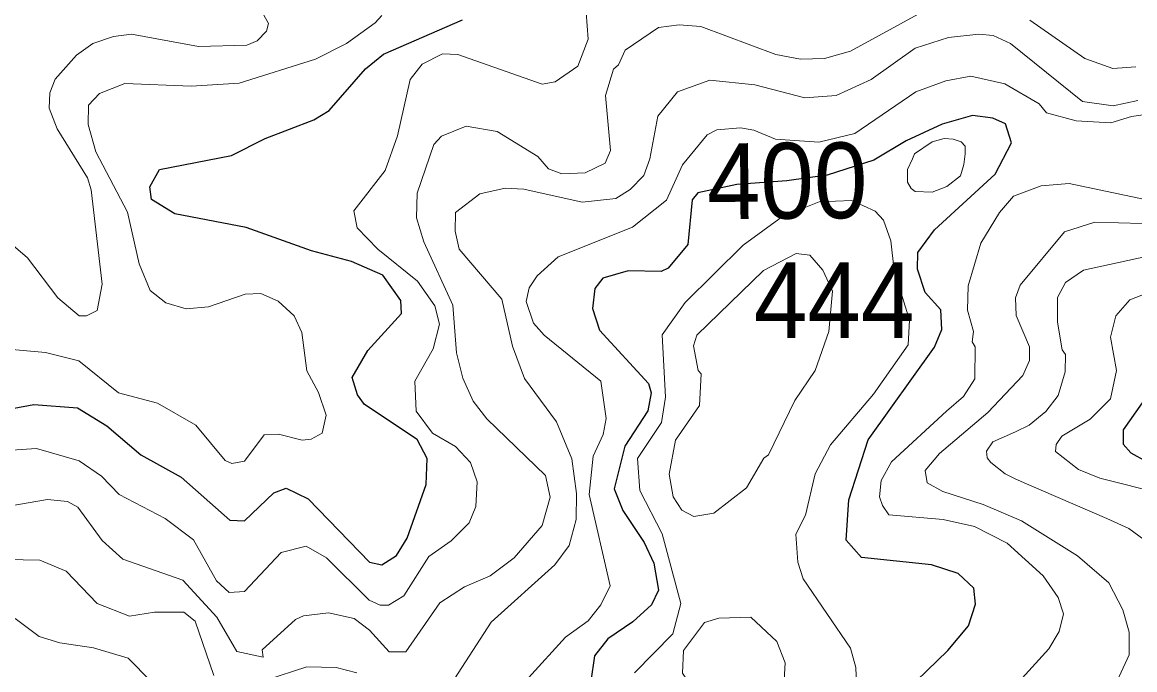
# Model space of a CAD drawing. Extents: x 673.6 to 698.9, y 7012 to 7040.1.
# Drawn here: x 685.993 to 687.168, y 7014.316 to 7015.001 of the extents above; entities that cross this region are included whole.
import ezdxf
from ezdxf.enums import TextEntityAlignment as Align

# ---------------------------------------------------------------- set-up
doc = ezdxf.new("R2010")
doc.units = 0
doc.header["$LTSCALE"] = 0.032
doc.layers.add('1', color=7, linetype='Continuous', lineweight=25)
doc.layers.add('2', color=7, linetype='Continuous', lineweight=13)
doc.layers.add('21', color=7, linetype='Continuous')
doc.layers.add('61', color=7, linetype='Continuous')

msp = doc.modelspace()

# ---------------------------------------------------------------- linework, layer by layer
at = {"layer": '1'}
for points in [[(685.9233, 7014.5815), (686.0049, 7014.5967), (686.0511, 7014.5932), (686.0823, 7014.5743), (686.1179, 7014.5436), (686.1606, 7014.5201), (686.2119, 7014.4745), (686.2274, 7014.474), (686.2584, 7014.5035), (686.2716, 7014.5085), (686.2948, 7014.4972), (686.3595, 7014.43), (686.3726, 7014.4275), (686.3882, 7014.4372), (686.3992, 7014.4555), (686.4194, 7014.5121), (686.4205, 7014.5397), (686.4098, 7014.5597), (686.3541, 7014.5968), (686.3469, 7014.6071), (686.3411, 7014.6251), (686.3577, 7014.6536), (686.3933, 7014.6929), (686.3927, 7014.7067), (686.3738, 7014.7335), (686.3404, 7014.7478), (686.2983, 7014.7589), (686.2292, 7014.7838), (686.154, 7014.7982), (686.1294, 7014.8132), (686.1274, 7014.8268), (686.1379, 7014.8451), (686.2139, 7014.8598), (686.2492, 7014.8779), (686.3009, 7014.8976), (686.317, 7014.9074), (686.3552, 7014.9512), (686.3742, 7014.967), (686.4576, 7015.0031)], [(686.9151, 7014.2833), (686.9702, 7014.3369), (686.9923, 7014.363), (686.9995, 7014.3858), (686.9979, 7014.4028), (686.9813, 7014.4182), (686.9531, 7014.4274), (686.8793, 7014.4351), (686.8629, 7014.4535), (686.8658, 7014.496), (686.8863, 7014.5595), (686.9563, 7014.6574), (686.964, 7014.6759), (686.9628, 7014.6968), (686.9463, 7014.7151), (686.9383, 7014.7397), (686.9386, 7014.7574), (686.9561, 7014.7813), (687.0204, 7014.84), (687.0375, 7014.873), (687.0314, 7014.8931), (687.018, 7014.8991), (686.9964, 7014.9021), (686.9643, 7014.8928), (686.9264, 7014.8751), (686.8921, 7014.8547), (686.8428, 7014.839), (686.8004, 7014.833), (686.7475, 7014.829), (686.7062, 7014.8205), (686.7002, 7014.813), (686.6956, 7014.7657), (686.6748, 7014.7408), (686.6675, 7014.7373), (686.6326, 7014.738), (686.606, 7014.7303), (686.5975, 7014.7194), (686.5949, 7014.6983), (686.6024, 7014.6751), (686.6541, 7014.6188), (686.6569, 7014.6092), (686.6535, 7014.5902), (686.6292, 7014.5528), (686.618, 7014.5076), (686.6272, 7014.4848), (686.6496, 7014.4508), (686.6597, 7014.4291), (686.6647, 7014.4007), (686.6574, 7014.385), (686.6377, 7014.367), (686.6113, 7014.3493), (686.597, 7014.3312), (686.5932, 7014.3046)], [(687.1757, 7014.5984), (687.1555, 7014.5698), (687.1554, 7014.5548), (687.1637, 7014.5456), (687.1802, 7014.5365)]]:
    msp.add_lwpolyline(points, dxfattribs=at)
at = {"layer": '2'}
for points in [[(685.9029, 7014.6617), (686.0172, 7014.6518), (686.0525, 7014.643), (686.0943, 7014.6091), (686.1358, 7014.5982), (686.1761, 7014.5749), (686.2071, 7014.5377), (686.214, 7014.5343), (686.2276, 7014.5369), (686.2484, 7014.5646), (686.2633, 7014.5655), (686.2886, 7014.559), (686.2981, 7014.56), (686.3097, 7014.5665), (686.3137, 7014.5853), (686.3056, 7014.6095), (686.2933, 7014.6324), (686.288, 7014.6728), (686.28, 7014.6903), (686.263, 7014.7058), (686.2447, 7014.7141), (686.2284, 7014.7134), (686.1895, 7014.7), (686.1659, 7014.6979), (686.1445, 7014.7043), (686.1278, 7014.7171), (686.1164, 7014.7453), (686.1038, 7014.8), (686.0704, 7014.8636), (686.0624, 7014.8926), (686.0628, 7014.913), (686.0743, 7014.9254), (686.101, 7014.9359), (686.1713, 7014.9329), (686.222, 7014.9362), (686.3025, 7014.9617), (686.3354, 7014.9782), (686.3657, 7014.9998), (686.3724, 7015.0078)], [(685.9656, 7014.5475), (686.008, 7014.5501), (686.053, 7014.5372), (686.0765, 7014.5209), (686.0953, 7014.5015), (686.1439, 7014.4763), (686.1738, 7014.4539), (686.198, 7014.4103), (686.2115, 7014.3981), (686.2277, 7014.399), (686.2661, 7014.4404), (686.2926, 7014.4472), (686.3143, 7014.4349), (686.3591, 7014.3901), (686.3708, 7014.3848), (686.3796, 7014.3848), (686.3959, 7014.3946), (686.4223, 7014.4363), (686.4457, 7014.4526), (686.4648, 7014.4718), (686.4717, 7014.4889), (686.4731, 7014.5149), (686.4661, 7014.5355), (686.4503, 7014.5522), (686.426, 7014.5666), (686.4088, 7014.5896), (686.4075, 7014.6213), (686.4269, 7014.6555), (686.4336, 7014.6816), (686.4285, 7014.7008), (686.4102, 7014.727), (686.3682, 7014.7608), (686.3464, 7014.7833), (686.343, 7014.8014), (686.3762, 7014.8441), (686.3892, 7014.8807), (686.4025, 7014.9399), (686.4152, 7014.9561), (686.4367, 7014.9671), (686.4527, 7014.9665), (686.5419, 7014.9353), (686.5558, 7014.9377), (686.5795, 7014.954), (686.5906, 7014.9826), (686.5883, 7015.0109)], [(686.2481, 7015.008), (686.2529, 7014.9992), (686.2507, 7014.991), (686.2408, 7014.9808), (686.2299, 7014.9764), (686.1791, 7014.9748), (686.1083, 7014.9878), (686.089, 7014.9855), (686.0673, 7014.978), (686.0501, 7014.9656), (686.0277, 7014.9405), (686.0221, 7014.9261), (686.0214, 7014.9098), (686.0297, 7014.8879), (686.0617, 7014.8361), (686.0656, 7014.8235), (686.0771, 7014.7239), (686.0719, 7014.696), (686.0606, 7014.6905), (686.0528, 7014.6905), (686.0304, 7014.7094), (685.9985, 7014.7518), (685.9679, 7014.7775)], [(686.9466, 7015.0133), (686.8676, 7014.9699), (686.84, 7014.9622), (686.8147, 7014.9616), (686.7887, 7014.9666), (686.7095, 7014.9962), (686.6866, 7014.9978), (686.6646, 7014.9951), (686.6297, 7014.9709), (686.6224, 7014.9557), (686.6171, 7014.9511), (686.6088, 7014.9233), (686.6142, 7014.8651), (686.6083, 7014.8517), (686.5874, 7014.8413), (686.5626, 7014.8404), (686.5487, 7014.8458), (686.5372, 7014.8586), (686.4943, 7014.8851), (686.4616, 7014.8909), (686.4356, 7014.8801), (686.4274, 7014.8713), (686.4098, 7014.8199), (686.4091, 7014.794), (686.417, 7014.7684), (686.4476, 7014.7017), (686.4515, 7014.6514), (686.4582, 7014.6244), (686.4692, 7014.6001), (686.4833, 7014.5816), (686.5453, 7014.5218), (686.5503, 7014.4988), (686.542, 7014.469), (686.5124, 7014.4347), (686.487, 7014.4156), (686.4597, 7014.4042), (686.4338, 7014.3871), (686.3979, 7014.3355), (686.3804, 7014.3355), (686.3597, 7014.3584), (686.3432, 7014.3707), (686.3162, 7014.3765)], [(687.1688, 7014.9534), (687.1447, 7014.9518), (687.1152, 7014.9623), (687.0571, 7015.0028)], [(687.1709, 7014.9178), (687.1448, 7014.9123), (687.1126, 7014.9169), (687.0365, 7014.9782), (687.0182, 7014.9864), (687.0032, 7014.9879), (686.9712, 7014.9846), (686.936, 7014.973), (686.8895, 7014.9401), (686.8525, 7014.923), (686.8192, 7014.9206), (686.7664, 7014.9343), (686.7191, 7014.9392), (686.6847, 7014.9272), (686.6639, 7014.9014), (686.6555, 7014.8561), (686.6492, 7014.8387), (686.6348, 7014.824), (686.6197, 7014.8142), (686.5842, 7014.8104), (686.5225, 7014.8243), (686.5027, 7014.8251), (686.4761, 7014.8193), (686.4502, 7014.7995), (686.4501, 7014.7797), (686.4544, 7014.7608), (686.4994, 7014.708), (686.5104, 7014.6582), (686.5234, 7014.6243), (686.5572, 7014.5783), (686.5733, 7014.5395), (686.5783, 7014.5027), (686.5777, 7014.4752), (686.5704, 7014.4478), (686.5553, 7014.4275), (686.4879, 7014.3666), (686.4416, 7014.2949)], [(687.1985, 7014.9058), (687.1643, 7014.9009), (687.1424, 7014.8943), (687.106, 7014.8963), (687.0747, 7014.905), (687.0668, 7014.9142), (687.0304, 7014.9355), (686.9947, 7014.9436), (686.9682, 7014.9385), (686.9367, 7014.927), (686.872, 7014.8829), (686.834, 7014.8738), (686.7885, 7014.877), (686.7656, 7014.8867), (686.7513, 7014.8891), (686.7264, 7014.8868), (686.7162, 7014.8816), (686.6901, 7014.85), (686.6733, 7014.8126), (686.6374, 7014.784), (686.5587, 7014.7528), (686.5367, 7014.7326), (686.5283, 7014.7199), (686.525, 7014.7056), (686.5329, 7014.6828), (686.5441, 7014.6699), (686.6037, 7014.6212), (686.6096, 7014.582), (686.6063, 7014.565), (686.5956, 7014.5422), (686.5916, 7014.5017), (686.6137, 7014.4051), (686.604, 7014.3851), (686.5904, 7014.3681), (686.5667, 7014.351), (686.5275, 7014.3079)], [(687.0487, 7014.3077), (687.0771, 7014.3385), (687.0878, 7014.3568), (687.0925, 7014.3756), (687.0867, 7014.3928), (687.071, 7014.4156), (687.033, 7014.4502), (686.9986, 7014.4677), (686.9655, 7014.4752), (686.9081, 7014.4801), (686.9012, 7014.49), (686.8982, 7014.4993), (686.9001, 7014.5165), (686.911, 7014.5363), (686.9691, 7014.5897), (686.9869, 7014.6052), (686.999, 7014.6237), (686.9991, 7014.6575), (686.9959, 7014.663), (686.9973, 7014.6739), (686.9912, 7014.6964), (686.9919, 7014.7221), (687.0053, 7014.767), (687.0248, 7014.7997), (687.0396, 7014.8169), (687.0688, 7014.8277), (687.0986, 7014.8301), (687.1771, 7014.8137)], [(686.8742, 7014.2923), (686.8733, 7014.3189), (686.8676, 7014.3392), (686.8176, 7014.4127), (686.8118, 7014.4301), (686.8099, 7014.4599), (686.8199, 7014.4797), (686.8302, 7014.5236), (686.8464, 7014.554), (686.8919, 7014.6078), (686.9286, 7014.6596), (686.93, 7014.6859), (686.9137, 7014.7384), (686.9102, 7014.7697), (686.9024, 7014.7916), (686.8935, 7014.8011), (686.8688, 7014.8121), (686.8346, 7014.8109), (686.7956, 7014.7954), (686.7541, 7014.765), (686.6928, 7014.7046), (686.6688, 7014.6703), (686.672, 7014.6046), (686.6681, 7014.5777), (686.6425, 7014.5396), (686.645, 7014.5057), (686.6687, 7014.46), (686.6885, 7014.3864), (686.6798, 7014.3545), (686.6394, 7014.3133)], [(687.0482, 7014.4739), (687.0077, 7014.4912), (686.9649, 7014.5048), (686.9486, 7014.5139), (686.9464, 7014.527), (686.9616, 7014.5448), (687.0126, 7014.5882), (687.0494, 7014.6274), (687.0566, 7014.6431), (687.0566, 7014.6577), (687.0426, 7014.6908), (687.0419, 7014.7094), (687.0467, 7014.7229), (687.0936, 7014.779), (687.1256, 7014.7892), (687.2007, 7014.7873)], [(687.1772, 7014.4541), (687.1615, 7014.4657), (687.1382, 7014.4763), (687.0511, 7014.5141), (687.0409, 7014.5184), (687.0308, 7014.5235), (687.0158, 7014.5356), (687.012, 7014.5405), (687.0111, 7014.5475), (687.0177, 7014.5574), (687.0418, 7014.568), (687.0564, 7014.575), (687.0738, 7014.5894), (687.087, 7014.6061), (687.0944, 7014.6313), (687.0945, 7014.6497), (687.0912, 7014.6545), (687.0863, 7014.6838), (687.0863, 7014.7097), (687.0945, 7014.7257), (687.1136, 7014.7385), (687.2186, 7014.7616)], [(687.1959, 7014.7203), (687.1624, 7014.7073), (687.1476, 7014.6904), (687.1423, 7014.6678), (687.1486, 7014.6326), (687.142, 7014.6028), (687.1208, 7014.5813), (687.0907, 7014.5632)], [(687.0907, 7014.5632), (687.0846, 7014.5545), (687.0841, 7014.5472), (687.1082, 7014.5279), (687.1307, 7014.5188), (687.1576, 7014.5122)], [(687.1576, 7014.5122), (687.1933, 7014.503)], [(686.2196, 7014.3358), (686.1982, 7014.3722), (686.1625, 7014.411), (686.0991, 7014.4334), (686.0773, 7014.4529), (686.0515, 7014.4882), (686.0407, 7014.4942), (686.0194, 7014.4965), (685.8966, 7014.4752)], [(687.1404, 7014.4085), (687.1073, 7014.4369), (687.0482, 7014.4739)], [(686.1952, 7014.3106), (686.1753, 7014.368), (686.1633, 7014.3772), (686.1323, 7014.3773), (686.1061, 7014.3732), (686.0719, 7014.3866), (686.0392, 7014.4208), (686.0113, 7014.4323), (685.9231, 7014.4341)], [(687.127, 7014.2818), (687.1472, 7014.3003), (687.1618, 7014.3322), (687.1618, 7014.3563), (687.1552, 7014.3798), (687.1404, 7014.4085)], [(686.1839, 7014.1906), (686.1665, 7014.2055), (686.1567, 7014.222), (686.1286, 7014.3045), (686.1046, 7014.3289), (686.0682, 7014.3397), (686.0324, 7014.3448), (686.0105, 7014.3515), (685.9852, 7014.3705)], [(686.3162, 7014.3765), (686.2899, 7014.3734), (686.2815, 7014.3697), (686.2461, 7014.3375), (686.2474, 7014.3299), (686.2196, 7014.3358)], [(686.346, 7014.3134), (686.3243, 7014.3189), (686.2932, 7014.3197), (686.2499, 7014.3055)]]:
    msp.add_lwpolyline(points, dxfattribs=at)
for points in [[(686.9329, 7014.8562), (686.9277, 7014.845), (686.9277, 7014.8316), (686.9315, 7014.8249), (686.9359, 7014.8219), (686.9538, 7014.8212), (686.9694, 7014.8272), (686.9836, 7014.8383), (686.9873, 7014.8502), (686.9888, 7014.8614), (686.9888, 7014.8696), (686.9843, 7014.8741), (686.9761, 7014.877), (686.9665, 7014.8778), (686.9538, 7014.8741), (686.9352, 7014.8614)], [(686.8448, 7014.6738), (686.8304, 7014.6328), (686.8088, 7014.6009), (686.7809, 7014.5437), (686.7759, 7014.5399), (686.7576, 7014.5086), (686.7233, 7014.4818), (686.702, 7014.4785), (686.6895, 7014.4851), (686.6803, 7014.4993), (686.6762, 7014.5232), (686.6828, 7014.5589), (686.7082, 7014.5955), (686.7098, 7014.6292), (686.7065, 7014.6327), (686.7016, 7014.6587), (686.7052, 7014.67), (686.7758, 7014.7384), (686.8103, 7014.7561), (686.8245, 7014.7544), (686.8382, 7014.7385), (686.8487, 7014.7164)], [(686.7899, 7014.3462), (686.7622, 7014.3722), (686.7286, 7014.3709), (686.7133, 7014.3665), (686.691, 7014.3368), (686.6902, 7014.3128), (686.7045, 7014.2913), (686.7183, 7014.2822), (686.7523, 7014.2747), (686.7719, 7014.2738), (686.7856, 7014.2822), (686.797, 7014.2996), (686.7986, 7014.3239)]]:
    msp.add_lwpolyline(points, close=True, dxfattribs=at)

# ---------------------------------------------------------------- texts
at = {"layer": '21', "width": 0.95}
msp.add_text('444', height=0.08, dxfattribs=at).set_placement((686.7655, 7014.6669))
at = {"layer": '61', "width": 0.95}
msp.add_text('400', height=0.08, rotation=0.402, dxfattribs=at).set_placement((686.8009, 7014.7931), align=Align.CENTER)

doc.saveas('drawing.dxf')
